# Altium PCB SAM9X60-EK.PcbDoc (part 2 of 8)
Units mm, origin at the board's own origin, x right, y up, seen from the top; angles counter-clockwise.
Board outline 150 x 125 mm, 4 copper layers (L1 - Top Layer, L2 - GND, L3 - PWR, L4 - Bottom Layer), stack 1.52 mm thick; 566 components, 500 nets, 2132 pads, 1038 vias.
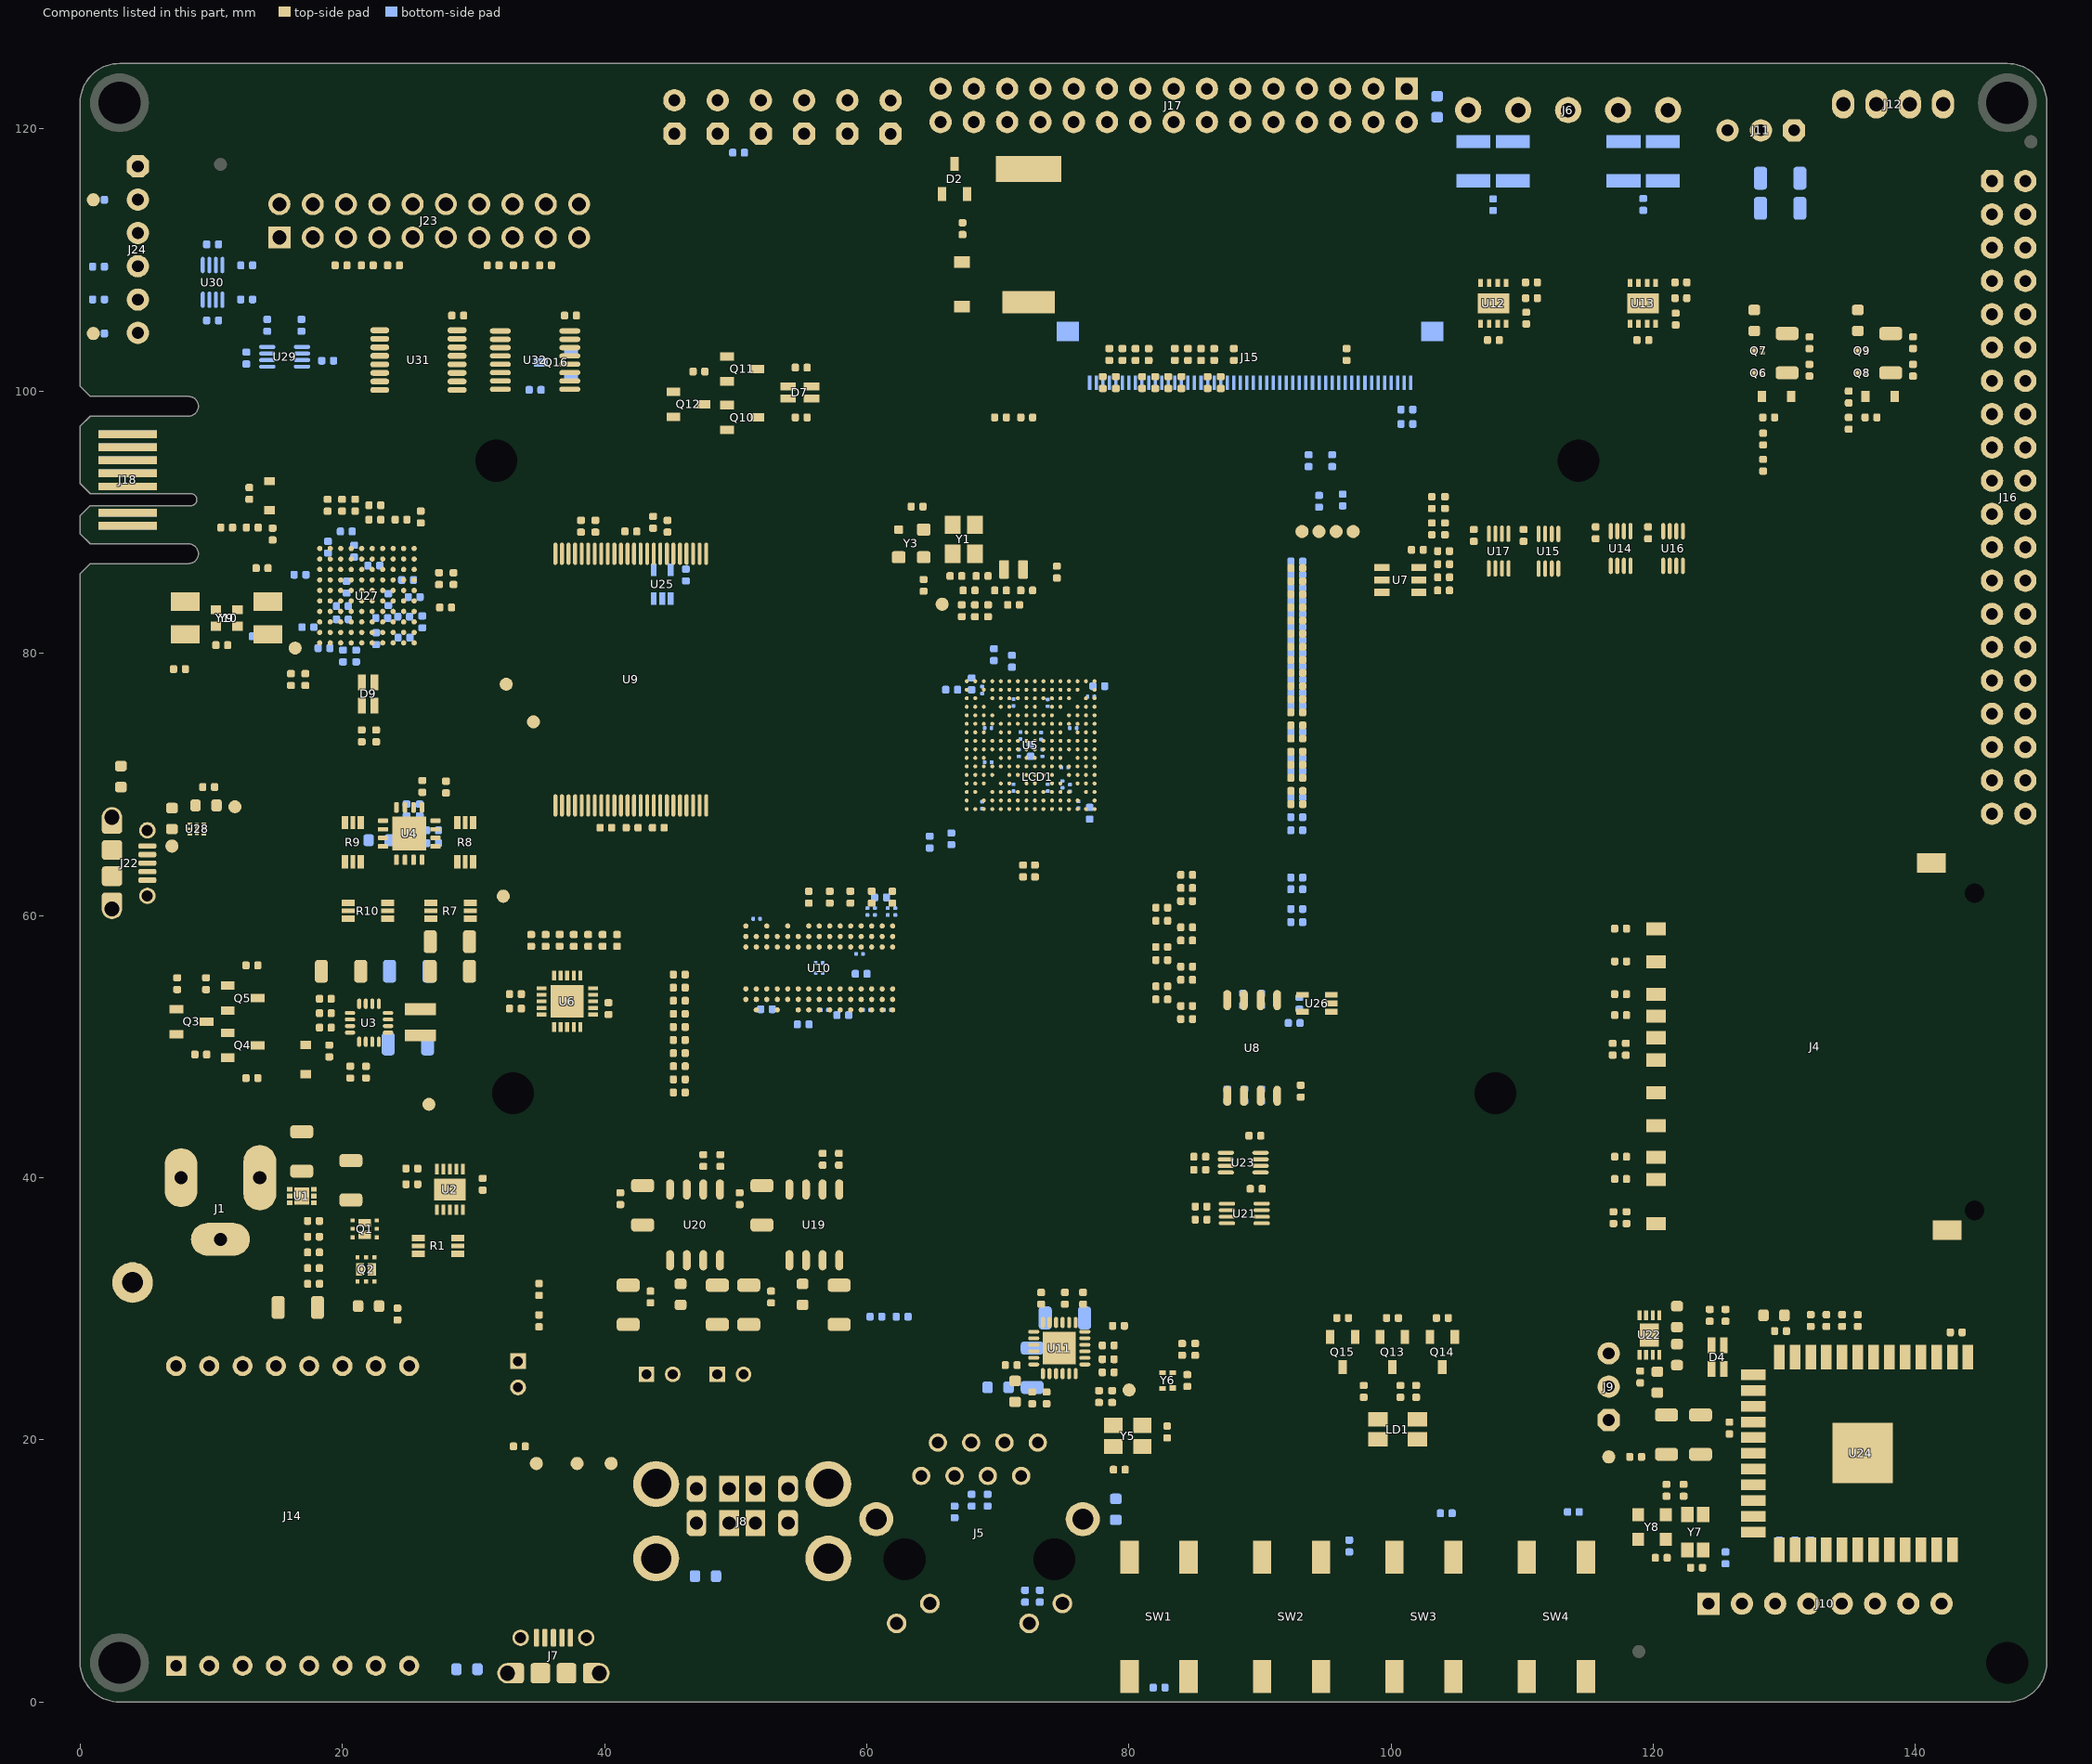
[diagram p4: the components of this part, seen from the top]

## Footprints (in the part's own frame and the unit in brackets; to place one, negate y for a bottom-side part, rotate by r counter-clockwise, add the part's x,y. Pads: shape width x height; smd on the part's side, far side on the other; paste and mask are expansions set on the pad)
10067847-001RLF [mm]
  rect 1x1.5 smd: 1(6.475,12.15) 2(3.975,12.15) 3(0.675,12.15) 4(-1.025,12.15) 5(-3.525,12.15) 6(-6.025,12.15) 7(-8.45,12.15) 8(-10.15,12.15) 9(8.975,12.15) 10(2.325,12.15) 11(-13.5,12.15)
  round 0 hole 1.5 unplated mask+0.05: 1.5mm(-12.5,-12.15) 1.5mm(11.7,-12.15)
  rect 1.5x2.2 smd: 12(-14,-10.05) 12(14,-8.85)
  L1 - Top Layer keep-out region: 8.425,1.05 9.525,1.05 9.525,3.05 8.425,3.05
  L1 - Top Layer keep-out region: 0.55,2.75 2.45,2.75 2.45,5.25 0.55,5.25
  L1 - Top Layer keep-out region: 5.925,3.55 7.025,3.55 7.025,6.05 5.925,6.05
  L1 - Top Layer keep-out region: 3.425,3.25 4.525,3.25 4.525,5.25 3.425,5.25
  L1 - Top Layer keep-out region: -1.575,2.75 -0.475,2.75 -0.475,4.75 -1.575,4.75
  L1 - Top Layer keep-out region: -4.075,3.15 -2.975,3.15 -2.975,5.15 -4.075,5.15
  L1 - Top Layer keep-out region: -6.575,3.15 -5.475,3.15 -5.475,5.15 -6.575,5.15
  L1 - Top Layer keep-out region: -15.1,-3.948 -13.9,-3.948 -13.9,2.352 -15.1,2.352
  L1 - Top Layer keep-out region: -9,3.15 -7.9,3.15 -7.9,5.15 -9,5.15
  L1 - Top Layer keep-out region: -10.7,3.15 -9.6,3.15 -9.6,5.15 -10.7,5.15
  silkscreen extent -15,-17.85 15,13.3, body extent -14.23,-17.65 14.22,12.6, height 2.9
"BUMP_ ESSENTRA_RBS-35_CYLINDRICAL_CLEAR_D9.50H4.8" [mm] "ESSENTRA Bumpon Rubber Pad D9.5H4.8"
  silkscreen extent -4.95,-4.95 4.95,4.95, body extent -4.77,-4.75 4.72,4.75, height 4.8
CAP_AX_P8.3L11.7D6.8H1.8 [mm]
  rect 5x2 smd: 1(0,5.075)
  rect 4x1.7 smd: 2(0,-5.075)
  silkscreen extent -3.5,-3.57 3.83,5.31, body extent -3.4,-5.73 3.4,5.58, height 1.71
CAP_C_0201 [mm] "Chip Capacitor, 2-Leads, Body 0.6x0.3mm, IPC Medium Density"
  rrect50% 0.275x0.3 smd mask+0.064: 1(-0.262,0) 2(0.262,0)
  body extent -0.3,-0.15 0.3,0.15, height 0.28
CAP_C_0402 [mm] "Chip Capacitor, 2-Leads, Body 1.0x0.5mm, IPC High Density"
  rrect50% 0.55x0.6 smd: 1(-0.45,0) 2(0.45,0)
  body extent -0.5,-0.3 0.5,0.3, height 0.2
CAP_C_0603 [mm] "Chip Capacitor, 2-Leads, Body 1.6x0.8mm, IPC Medium Density"
  rrect50% 0.8x0.9 smd: 1(-0.8,0) 2(0.8,0)
  silkscreen extent -0.1,-0.37 0.1,0.38, body extent -0.8,-0.4 0.8,0.4, height 0.3
CAP_C_1206 [mm] "Chip Capacitor, 2-Leads, Body 3.2x1.6mm, IPC Medium Density"
  rrect50% 1x1.75 smd: 1(-1.5,0) 2(1.5,0)
  silkscreen extent -0.6,-0.77 0.6,0.77, body extent -1.6,-0.8 1.6,0.8, height 1
CAP_RAD_P2D5H12.5 [mm] "Capacitor, Electrolytic, Radial; Body P=2.0mm, D=5mm, H=12.5mm"
  rect 1.2x1.2 hole 0.75: 1(-1,0)
  round 1.2 hole 0.75: 2(1,0)
  silkscreen extent -2.5,-2.5 2.5,2.5, body extent -2.5,-2.5 2.5,2.5, height 12.5
CDFN-4_3.2X2.5 [mil] "Oscillator DSC60X1C"
  rrect30% 26x26 smd: 1(-37.5,41.5)
  rrect30% 40x36 smd paste-2: 2(-37.5,-41.5) 3(37.5,-41.5) 4(37.5,41.5)
  L1 - Top Layer region: -53.5,23.5 -55.03,23.8 -56.33,24.67 -57.2,25.97 -57.5,27.5 -57.5,27.5 -57.5,55.5 -57.2,57.03 -56.33,58.33 -55.03,59.2 -53.5,59.5 -53.5,59.5 -27.5,59.5 -17.5,49.5 -17.5,27.5 -17.8,25.97 -18.67,24.67 -19.97,23.8 -21.5,23.5 -21.5,23.5
  silkscreen extent -68,-73 68,73, body extent -49,-63 49,63, height 34
CON_EDGE-CARD_PCB_RA_MEC1-108-02-F-D-RA1-SL [mm] "connector matching PCB pads"
  rect 0.6x4.45 smd far side paste-1 mask+0.05: 1(0,0) 3(-1,0) 7(-3,0) 9(-4,0) 11(-5,0) 13(-6,0) 15(-7,0)
  rect 0.6x4.45 smd paste-1 mask+0.05: 2(0,0) 4(-1,0) 8(-3,0) 10(-4,0) 12(-5,0) 14(-6,0) 16(-7,0)
  Keep-Out Layer lines w0.05: 3.655,-3.625 2.88,-2.85 2.88,4.64 ccw(c2.13,4.64) 1.38,4.64 1.38,-2.85 0.605,-3.625 -0.763,-3.625 -1.538,-2.85 -1.538,4.818 ccw(c-1.995,4.818) -2.452,4.818 -2.452,-2.85 ; -10.645,-3.625 -9.87,-2.85 -9.87,4.64 cw(c-9.12,4.64) -8.37,4.64 -8.37,-2.85 -7.595,-3.625 -3.227,-3.625 -2.452,-2.85 ; -2.451,-2.85 -2.452,-2.85
  body extent -7.3,-2.22 0.3,2.23, height 0.02
CON_FFC_0.5_FEMALE_1X50_SMD_OMR_XF2M-5015-1A [mm] "CONN FFC TOP/BOTTOM 50POS 0.50MM R/A"
  rect 0.25x1.1 smd: 1(12.25,-1.841) 2(11.75,-1.841) 3(11.25,-1.841) 4(10.75,-1.841) 5(10.25,-1.841) 6(9.75,-1.841) 7(9.25,-1.841) 8(8.75,-1.841) 9(8.25,-1.841) 10(7.75,-1.841) 11(7.25,-1.841) 12(6.75,-1.841) 13(6.25,-1.841) 14(5.75,-1.841) 15(5.25,-1.841) 16(4.75,-1.841) 17(4.25,-1.841) 18(3.75,-1.841) 19(3.25,-1.841) 20(2.75,-1.841) 21(2.25,-1.841) 22(1.75,-1.841) 23(1.25,-1.841) 24(0.75,-1.841) 25(0.25,-1.841) 26(-0.25,-1.841) 27(-0.75,-1.841) 28(-1.25,-1.841) 29(-1.75,-1.841) 30(-2.25,-1.841) 31(-2.75,-1.841) 32(-3.25,-1.841) 33(-3.75,-1.841) 34(-4.25,-1.841) 35(-4.75,-1.841) 36(-5.25,-1.841) 37(-5.75,-1.841) 38(-6.25,-1.841) 39(-6.75,-1.841) 40(-7.25,-1.841) 41(-7.75,-1.841) 42(-8.25,-1.841) 43(-8.75,-1.841) 44(-9.25,-1.841) 45(-9.75,-1.841) 46(-10.25,-1.841) 47(-10.75,-1.841) 48(-11.25,-1.841) 49(-11.75,-1.841) 50(-12.25,-1.841)
  rect 1.7x1.5 smd: MNT(-13.9,2.059) MNT(13.9,2.059)
  silkscreen extent -14.25,-1.89 14.25,0.56, body extent -14.55,-2.9 14.55,3, height 2
CON_JACK_POWER_TH_RA_MPD_EJ508A [mm] "CONN POWER JACK MALE 2.1MM CLSD"
  oval 2.5x5 hole 1 slot 3.5 at 90 deg: 1(3,0)
  oval 2.5x4.5 hole 1 slot 3 at 90 deg: 2(-3,0)
  oval 4.5x2.5 hole 1 slot 3 at 0 deg: 3(0,-4.7)
  silkscreen extent -10.79,-4.5 3.7,4.5, body extent -10.7,-4.9 3.7,4.5, height 11.1
CON_TERMINAL_2.54_1x4_TH_RA_PHO_1725672 [mm] "Terminal Block 2.54mm Pitch 1x4 PHO 1725672"
  oval 1.7x2.2 hole 1.1: 1(-3.81,0) 2(-1.27,0) 3(1.27,0) 4(3.81,0)
  silkscreen extent -5.51,-3.45 5.51,3.45, body extent -5.1,-2.99 5.2,3.23, height 8.64
CON_TERMINAL_3.81_1x5_TH_RA_PHO_1727049 [mm]
  round 2 hole 1.1: 1(-7.62,0) 2(-3.81,0) 3(0,0) 4(3.81,0) 5(7.62,0)
  silkscreen extent -9.91,-4.06 9.91,3.94, body extent -9.53,-3.74 9.52,3.56, height 8.5
CON_TP_TH_V_BLK_KEC_5011 [mm] "TEST POINT PC MULTI PURPOSE BLK"
  round 3.1 hole 1.6: 1(0,0)
  silkscreen extent -1.85,-1.85 1.85,1.85, body extent -1.59,-1.59 1.59,1.59, height 8.13
CON_USB2.0-A_Dual_RCPT_TH_RA_AMN_AU-Y1008-2 [mm] "CONN USB 2.0 A DUAL RCPT TH R/A L=17.5mm, W=14.5mm, H=15.7mm"
  round 3.5 hole 2.3: 0(-6.57,-2.84) 0(-6.57,2.84) 0(6.57,-2.84) 0(6.57,2.84)
  rrect50% 1.5x2 hole 1: 1(-3.5,2.49) 4(3.5,2.49) 5(-3.5,-0.13) 8(3.5,-0.13)
  rect 1.5x2 hole 1: 2(-1,2.49) 3(1,2.49) 6(-1,-0.13) 7(1,-0.13)
  silkscreen extent -6.8,-13.34 6.8,4.56, body extent -7.85,-13.74 7.85,3.86, height 16.2
CON_USB_MICRO-AB_SMD_TH_RA_FCI_10118194-0001LF [mm] "FCI USB Micro-AB SMD RA L5W8.8H2.8"
  round 1.55 hole 1.15: 0(-3.505,0) 0(3.505,0)
  rrect30% 1.5x1.55 smd paste-0.051: 0(-3,0) 0(-1,0) 0(1,0) 0(3,0)
  round 1.25 hole 0.85: 0(-2.5,-2.7) 0(2.5,-2.7)
  rrect50% 0.4x1.35 smd paste-0.046 mask+0.05: 1(1.3,-2.7) 2(0.65,-2.7) 3(0,-2.7) 4(-0.65,-2.7) 5(-1.3,-2.7)
  Keep-Out Layer board cut-out: 3.81,1.452 4.102,1.51 4.349,1.675 4.514,1.922 4.572,2.214 4.572,2.214 4.514,2.505 4.349,2.753 4.102,2.918 3.81,2.976 3.81,2.976 -3.81,2.976 -4.102,2.918 -4.349,2.753 -4.514,2.505 -4.572,2.214 -4.572,2.214 -4.514,1.922 -4.349,1.675 -4.102,1.51 -3.81,1.452 -3.81,1.452
  Keep-Out Layer board cut-out: 3.81,1.452 4.102,1.51 4.349,1.675 4.514,1.922 4.572,2.214 4.572,2.214 4.514,2.505 4.349,2.753 4.102,2.918 3.81,2.976 3.81,2.976 -3.81,2.976 -4.102,2.918 -4.349,2.753 -4.514,2.505 -4.572,2.214 -4.572,2.214 -4.514,1.922 -4.349,1.675 -4.102,1.51 -3.81,1.452 -3.81,1.452
  silkscreen extent -4.22,-3.1 4.23,-1.07, body extent -4.02,-2.89 4.02,2.69, height 2.74
CRYSTAL_ABM8G [mil]
  rect 55x47 smd: 1(-43.5,-33.5) 2(43.5,-33.5) 3(43.5,33.5) 4(-43.5,33.5)
  silkscreen extent -81,-67 81,67, body extent -63,-49 63,49, height 40
CRYSTAL_ABS06 [mm] "Crystal Abracon ABS07"
  rrect20% 0.75x1.4 smd: 1(-0.725,0) 2(0.725,0)
  silkscreen extent -1.35,-0.95 1.35,0.95, body extent -1,-0.61 1,0.61, height 0.6
CRYSTAL_L3.2W2.5H0.8 [mm] "L=3.2mm, W=2.5mm, H=0.8mm"
  rect 1.4x1.15 smd: 1(-1.1,-0.8) 2(1.1,-0.8) 3(1.1,0.8) 4(-1.1,0.8)
  silkscreen extent -2.1,-1.68 2.1,1.68, body extent -1.6,-1.25 1.6,1.25, height 0.8
CRYSTAL_L7.5W5.2H1.4 [mm]
  rect 2.2x1.4 smd: 1(-3.15,-1.25) 2(-3.15,1.25) 3(3.15,1.25) 4(3.15,-1.25)
  silkscreen extent -4,-2.9 4,2.9, body extent -3.7,-2.6 3.7,2.6, height 1.45
"DFN-4_VFLGA_1.6 X 1.2" [mm] "DFN, 4-Leads, Body 1.60x1.20mm, Pitch 1.25mm, IPC Medium Density"
  rect 0.43x0.5 smd: 1(-0.56,-0.375)
  rect 0.35x0.5 smd: 2(0.6,-0.375) 3(0.6,0.375) 4(-0.6,0.375)
  silkscreen extent -0.9,-0.95 0.9,0.95, body extent -0.8,-0.6 0.8,0.6, height 0.61
DFN-6_1.2X1.2 [mm] "DFN, 6-Leads, Body 1.2x1.2mm (max), Pitch 0.65"
  rect 0.18x0.35 smd: 1(-0.4,-0.525) 2(0,-0.525) 3(0.4,-0.525) 4(0.4,0.525) 5(0,0.525) 6(-0.4,0.525)
  rect 0.94x0.3 smd: 7(0,0)
  silkscreen extent -1,-0.4 1,0.4, body extent -0.62,-0.62 0.63,0.63, height 0.6
DFN-6_2x1.6_EP0.4x0.35 [mm] "DFN, 6-Leads, Body 2x1.6mm (max), Pitch 0.5"
  rect 0.36x0.43 smd mask+0.038: 1(-0.5,-0.925) 2(0,-0.925) 3(0.5,-0.925) 4(0.5,0.925) 5(0,0.925) 6(-0.5,0.925)
  rect 1.3x1.15 smd mask+0.038: 7(0,0)
  silkscreen extent -0.95,-0.4 0.95,0.4, body extent -0.8,-1 0.8,1, height 1
DFN-8_2x3 [mm] "DFN, 8-Leads, Body 3.0x2.0mm (max), Pitch 0.5"
  rect 0.3x0.75 smd mask+0.05: 1(-0.75,-1.5) 2(-0.25,-1.5) 3(0.25,-1.5) 4(0.75,-1.5) 5(0.75,1.5) 6(0.25,1.5) 7(-0.25,1.5) 8(-0.75,1.5)
  rect 1.45x1.75 smd mask+0.075: 9(0,0)
  silkscreen extent -1.1,-0.8 1.1,0.8, body extent -1,-1.5 1,1.5, height 1
DFN-8_3x3_EP2.4X1.55 [mm] "DFN, 8-Leads, Body 3.0x3.0mm (max), Pitch 0.65mm, IPC Medium Density"
  rect 0.35x0.6 smd: 1(-0.975,-1.55) 2(-0.325,-1.55) 3(0.325,-1.55) 4(0.975,-1.55) 5(0.975,1.55) 6(0.325,1.55) 7(-0.325,1.55) 8(-0.975,1.55)
  rect 2.4x1.55 smd: 9(0,0)
  silkscreen extent -1.6,-1.5 1.6,1.5, body extent -1.5,-1.5 1.5,1.5, height 0.61
DFN-10_3x3 [mm] "DFN, 10-Leads, Body 3.0x3.0mm (max), Pitch 0.50mm, IPC Medium Density"
  rect 0.8x0.3 smd paste-0.038 mask+0.05: 1(-1.55,1) 2(-1.55,0.5) 3(-1.55,0) 4(-1.55,-0.5) 5(-1.55,-1) 6(1.55,-1) 7(1.55,-0.5) 8(1.55,0) 9(1.55,0.5) 10(1.55,1)
  rect 1.65x2.38 smd paste-0.305: 11(0,0)
  silkscreen extent -1.6,-1.6 1.6,1.6, body extent -1.56,-1.55 1.56,1.55, height 0.8
HDR_F_2.54_1x3 [mm]
  oct 1.7x1.7 hole 0.9: 1(-2.54,0)
  round 1.7 hole 0.9: 2(0,0) 3(2.54,0)
  silkscreen extent -4,-1.5 4,1.5, body extent -3.81,-1.27 3.81,1.27, height 6.02
HDR_F_2.54_1X8 [mm] "Header Female Vertical 8 Way 2.54mm Pitch"
  rect 1.7x1.7 hole 0.9: 1(-8.89,0)
  round 1.7 hole 0.9: 2(-6.35,0) 3(-3.81,0) 4(-1.27,0) 5(1.27,0) 6(3.81,0) 7(6.35,0) 8(8.89,0)
  silkscreen extent -10.61,-1.4 10.59,1.4, body extent -10.41,-1.21 10.42,1.21, height 8.51
HDR_M_2.54_1x2 [mm] "Header Male Vertical 4 Way 2.54mm Pitch"
  oct 1.7x1.7 hole 0.9: 1(-1.27,0)
  round 1.7 hole 0.9: 2(1.27,0)
  silkscreen extent -2.6,-1.35 2.6,1.4, body extent -2.54,-1.27 2.54,1.27, height 5.94
HDR_M_2.54_1x3 [mm] "Header Male Vertical 4 Way P=2.54mm"
  oct 1.7x1.7 hole 0.9: 1(-2.54,0)
  round 1.7 hole 0.9: 2(0,0) 3(2.54,0)
  silkscreen extent -3.94,-1.4 3.96,1.4, body extent -3.8,-1.26 3.82,1.28, height 5.94
HDR_M_2.54_1x6 [mm] "Header Male Vertical 6 Way 2.54mm Pitch"
  oct 1.7x1.7 hole 0.9: 1(-6.35,0)
  round 1.7 hole 0.9: 2(-3.81,0) 3(-1.27,0) 4(1.27,0) 5(3.81,0) 6(6.35,0)
  silkscreen extent -7.75,-1.4 7.7,1.4, body extent -7.62,-1.27 7.62,1.27, height 8.38
HDR_M_2.54_2X10_S_TH_RA_OS_302-R201 [mil] "20 Positions Header Connector 0.100\" (2.54mm) Through Hole Gold"
  rect 66x66 hole 42: 1(-450,-50)
  round 66 hole 42: 2(-450,50) 3(-350,-50) 4(-350,50) 5(-250,-50) 6(-250,50) 7(-150,-50) 8(-150,50) 9(-50,-50) 10(-50,50) 11(50,-50) 12(50,50) 13(150,-50) 14(150,50) 15(250,-50) 16(250,50) 17(350,-50) 18(350,50) 19(450,-50) 20(450,50)
  silkscreen extent -658,-98 658,480, body extent -651,-63 651,471, height 359
HDR_M_2.54_2x15 [mm] "Header Male Vertical 2x10 Way 2.54mm Pitch"
  rect 1.7x1.7 hole 0.9: 1(-17.788,-1.27)
  round 1.7 hole 0.9: 2(-17.788,1.27) 3(-15.248,-1.27) 4(-15.248,1.27) 5(-12.708,-1.27) 6(-12.708,1.27) 7(-10.168,-1.27) 8(-10.168,1.27) 9(-7.628,-1.27) 10(-7.628,1.27) 11(-5.088,-1.27) 12(-5.088,1.27) 13(-2.548,-1.27) 14(-2.548,1.27) 15(-0.008,-1.27) 16(-0.008,1.27) 17(2.532,-1.27) 18(2.532,1.27) 19(5.072,-1.27) 20(5.072,1.27) 21(7.612,-1.27) 22(7.612,1.27) 23(10.152,-1.27) 24(10.152,1.27) 25(12.692,-1.27) 26(12.692,1.27) 27(15.232,-1.27) 28(15.232,1.27) 29(17.772,-1.27) 30(17.772,1.27)
  silkscreen extent -19.31,-2.79 19.42,2.79, body extent -19.06,-2.54 19.04,2.54, height 8.5
HDR_M_2.54_2x20 [mm] "Header Male Vertical 2x20 Way 2.54mm Pitch"
  oct 1.7x1.7 hole 0.9: 1(-24.13,-1.27)
  round 1.7 hole 0.9: 2(-24.13,1.27) 3(-21.59,-1.27) 4(-21.59,1.27) 5(-19.05,-1.27) 6(-19.05,1.27) 7(-16.51,-1.27) 8(-16.51,1.27) 9(-13.97,-1.27) 10(-13.97,1.27) 11(-11.43,-1.27) 12(-11.43,1.27) 13(-8.89,-1.27) 14(-8.89,1.27) 15(-6.35,-1.27) 16(-6.35,1.27) 17(-3.81,-1.27) 18(-3.81,1.27) 19(-1.27,-1.27) 20(-1.27,1.27) 21(1.27,-1.27) 22(1.27,1.27) 23(3.81,-1.27) 24(3.81,1.27) 25(6.35,-1.27) 26(6.35,1.27) 27(8.89,-1.27) 28(8.89,1.27) 29(11.43,-1.27) 30(11.43,1.27) 31(13.97,-1.27) 32(13.97,1.27) 33(16.51,-1.27) 34(16.51,1.27) 35(19.05,-1.27) 36(19.05,1.27) 37(21.59,-1.27) 38(21.59,1.27) 39(24.13,-1.27) 40(24.13,1.27)
  silkscreen extent -25.4,-2.54 25.4,2.54, body extent -25.4,-2.54 25.4,2.54, height 8.38
IND_C_0603 [mm] "Chip Inductor, 2-Leads, Body 1.6x0.8mm, IPC Medium Density"
  rrect50% 0.8x0.9 smd: 1(-0.8,0) 2(0.8,0)
  silkscreen extent -0.1,-0.35 0.1,0.35, body extent -0.8,-0.4 0.8,0.4, height 0.95
IND_C_1008 [mm]
  rect 0.9x2.4 smd mask+0.075: 1(-1,0) 2(1,0)
  silkscreen extent -0.25,-1.1 0.25,1.1, body extent -1.24,-1 1.26,1, height 1.2
J00-0045NL_RJ45_connector [mm] "J00-0061NL_RJ45_connector"
  round 1.4 / inner round 1.524 / far side round 1.4 hole 0.9: 1(-4.445,6.35) 2(-3.175,8.89) 3(-1.905,6.35) 4(-0.635,8.89) 5(0.635,6.35) 6(1.905,8.89) 7(3.175,6.35) 8(4.445,8.89)
  round 1.5 / inner round 1.524 / far side round 1.4 hole 1: 9(-6.325,-4.9) 10(-3.785,-3.38) 11(3.785,-4.9) 12(6.325,-3.38)
  round 2.6 / inner round 1.524 / far side round 2.6 hole 1.6: 13(-7.875,3.05) 14(7.875,3.05)
  round 2.3 / inner round 1.524 / far side round 2.3 hole 3.2 unplated: MH1(-5.715,0)
  round 2 / inner round 1.524 / far side round 2 hole 3.2 unplated: MH2(5.715,0)
  silkscreen extent -8.51,-11.3 8.51,11.05, body extent -8.12,-10.9 8.12,10.77, height 13.74
LABEL_Need_Help_Large [mm] "Need Help Label with Serial Number"
  silkscreen extent -25.4,-6.35 25.4,6.35, body extent -25.4,-6.35 25.4,6.35, height 0.3
LED_DUAL_SMD_2x1.25mm [mm] "LED 2X1.2MM RD/GN WTR CLR SMD"
  rect 1.2x0.6 smd: 1(0.9,0.475) 2(-0.9,0.475) 3(-0.9,-0.475) 4(0.9,-0.475)
  silkscreen extent -2.16,-1.07 1.8,1.08, body extent -0.81,-0.75 0.81,0.75, height 0.6
"MODULE ATWILC3000-MR110CA" [mm]
  rect 1.88x0.813 smd paste-9: 1(-7.31,8.05) 2(-7.31,6.85) 3(-7.31,5.65) 4(-7.31,4.45) 5(-7.31,3.25) 6(-7.31,2.05) 7(-7.31,0.85) 8(-7.31,-0.35) 9(-7.31,-1.55) 10(-7.31,-2.75) 11(-7.31,-3.95) 12(-7.31,-5.15) 13(-7.31,-6.35) 25(7.37,-6.35) 26(7.37,-5.15) 27(7.37,-3.95) 28(7.37,-2.75) 29(7.37,-1.55) 30(7.37,-0.35) 31(7.37,0.85) 32(7.37,2.05) 33(7.37,3.25) 34(7.37,4.45) 35(7.37,5.65) 36(7.37,6.85)
  rect 0.813x1.88 smd paste-9: 14(-5.97,-8.33) 15(-4.77,-8.33) 16(-3.57,-8.33) 17(-2.37,-8.33) 18(-1.17,-8.33) 19(0.03,-8.33) 20(1.23,-8.33) 21(2.43,-8.33) 22(3.63,-8.33) 23(4.83,-8.33) 24(6.03,-8.33)
  rect 4.6x4.6 smd paste-9: 37(0,0)
  silkscreen extent -7.75,-8.75 7.75,14.25, body extent -7.31,-8.33 7.37,14.05, height 2.73
OSCILLATOR_ASH7KW_L3.2W1.5H1 [mm]
  rect 0.95x1.15 smd: 1(-0.6,1.35) 2(-0.6,-1.35) 3(0.6,-1.35) 4(0.6,1.35)
  silkscreen extent -1,-0.53 1.05,0.52, body extent -0.75,-1.6 0.75,1.6, height 1
OSCILLATOR_DSC1001_L3.2W2.5H0.85 [mm] "Oscillator DSC1001"
  rect 0.9x1 smd: 1(-1.05,-0.95) 2(1.05,-0.95) 3(1.05,0.95) 4(-1.05,0.95)
  silkscreen extent -1.7,-1.35 1.7,1.35, body extent -1.6,-1.25 1.6,1.25, height 0.86
OSCILLATOR_DSC60000L2.5W2.0H0.89 [mm]
  rect 0.8x0.7 smd: 1(-0.825,-0.625) 2(0.825,-0.625) 3(0.825,0.625) 4(-0.825,0.625)
  silkscreen extent -1.5,-1.25 1.5,1.25, body extent -1.28,-0.97 1.22,1.03, height 0.82
PLCC-4_CLV1A-FKB [mm] "PLCC4 3 in 1 SMD LED"
  rect 1.5x1.1 smd: 1(-1.5,0.75) 2(-1.5,-0.75) 3(1.5,-0.75) 4(1.5,0.75)
  silkscreen extent -2.5,-1.55 2.5,1.55, body extent -1.75,-1.4 1.75,1.4, height 1.9
QFN-16_3X3 [mm] "QFN 16 pin P=0.5mm, L=3mm, W=3mm, H=0.9mm"
  oval 0.8x0.3 smd mask+0.05: 1(-1.45,0.75) 2(-1.45,0.25) 3(-1.45,-0.25) 4(-1.45,-0.75) 9(1.45,-0.75) 10(1.45,-0.25) 11(1.45,0.25) 12(1.45,0.75)
  oval 0.3x0.8 smd mask+0.05: 5(-0.75,-1.45) 6(-0.25,-1.45) 7(0.25,-1.45) 8(0.75,-1.45) 13(0.75,1.45) 14(0.25,1.45) 15(-0.25,1.45) 16(-0.75,1.45)
  silkscreen extent -1.7,-1.7 1.7,1.7, body extent -1.5,-1.5 1.5,1.5, height 0.9
QFN-20_4x4 [mm]
  rect 0.73x0.3 smd paste-0.075: 1(-1.965,1) 2(-1.965,0.5) 3(-1.965,0) 4(-1.965,-0.5) 5(-1.965,-1) 11(1.965,-1) 12(1.965,-0.5) 13(1.965,0) 14(1.965,0.5) 15(1.965,1)
  rect 0.3x0.73 smd paste-0.075: 6(-1,-1.965) 7(-0.5,-1.965) 8(0,-1.965) 9(0.5,-1.965) 10(1,-1.965) 16(1,1.965) 17(0.5,1.965) 18(0,1.965) 19(-0.5,1.965) 20(-1,1.965)
  rect 2.5x2.5 smd paste-0.75: 21(0,0)
  silkscreen extent -2.1,-2.1 2.1,2.1, body extent -2.02,-2.02 2.02,2.02, height 0.8
QFN-24_4X4 [mm]
  oval 0.85x0.3 smd mask+0.05: 1(-1.95,1.25) 2(-1.95,0.75) 3(-1.95,0.25) 4(-1.95,-0.25) 5(-1.95,-0.75) 6(-1.95,-1.25) 13(1.95,-1.25) 14(1.95,-0.75) 15(1.95,-0.25) 16(1.95,0.25) 17(1.95,0.75) 18(1.95,1.25)
  oval 0.3x0.85 smd mask+0.05: 7(-1.25,-1.95) 8(-0.75,-1.95) 9(-0.25,-1.95) 10(0.25,-1.95) 11(0.75,-1.95) 12(1.25,-1.95) 19(1.25,1.95) 20(0.75,1.95) 21(0.25,1.95) 22(-0.25,1.95) 23(-0.75,1.95) 24(-1.25,1.95)
  rect 2.5x2.5 smd paste-0.33 mask+0.05: 25(0,0)
  silkscreen extent -2.15,-2.15 2.15,2.15, body extent -2,-2 2,2, height 0.9
QSOP-16 [mm] "QSOP 16-Leads"
  oval 1.6x0.4 smd mask+0.05: 1(-2.65,2.223) 2(-2.65,1.588) 3(-2.65,0.953) 4(-2.65,0.318) 5(-2.65,-0.317) 6(-2.65,-0.952) 7(-2.65,-1.587) 8(-2.65,-2.222) 9(2.65,-2.222) 10(2.65,-1.587) 11(2.65,-0.952) 12(2.65,-0.317) 13(2.65,0.318) 14(2.65,0.953) 15(2.65,1.588) 16(2.65,2.223)
  silkscreen extent -2.77,-2.5 1.5,3.12, body extent -3.01,-2.49 3.01,2.49, height 1.71
RES_C_0201 [mm] "Chip Resistor, 2-Leads, Body 0.6x0.3mm, IPC Medium Density"
  rrect50% 0.275x0.3 smd mask+0.064: 1(-0.262,0) 2(0.262,0)
  body extent -0.3,-0.15 0.3,0.15, height 0.22
RES_C_0402 [mm] "Chip Resistor, 2-Leads, Body 1.0x0.5mm, IPC Medium Density"
  rrect50% 0.55x0.6 smd: 1(-0.45,0) 2(0.45,0)
  body extent -0.5,-0.3 0.5,0.3, height 0.2
RES_C_0603 [mm] "Chip Resistor, 2-Leads, Body 1.6x0.8mm, IPC Medium Density"
  rrect50% 0.8x0.9 smd: 1(-0.8,0) 2(0.8,0)
  silkscreen extent -0.1,-0.37 0.1,0.37, body extent -0.8,-0.4 0.8,0.4, height 0.3
RES_C_1206_SHUNT#1 [mm] "Chip Resistor, 2-Leads, Body 3.2x1.6mm, IPC Medium Density"
  rect 1x0.5 smd: 1(-1.5,-0.6) 1(-1.5,0.6) 2(1.5,-0.6) 2(1.5,0.6)
  rect 1x0.35 smd: 3(-1.5,0) 4(1.5,0)
  silkscreen extent -0.6,-0.77 0.6,0.78, body extent -1.6,-0.8 1.6,0.8, height 1
RES_C_1206_SHUNT#2 [mm] "Chip Resistor, 2-Leads, Body 3.2x1.6mm, IPC Medium Density"
  rect 1x0.5 smd mask+0.05: 1(-1.5,-0.6) 1(-1.5,0.6) 2(1.5,-0.6) 2(1.5,0.6)
  rect 1x0.35 smd mask+0.05: 3(-1.5,0) 4(1.5,0)
  silkscreen extent -0.6,-0.77 0.6,0.78, body extent -1.6,-0.8 1.6,0.8, height 1
RES_C_1210 [mm] "Chip Resistor, 2-Leads, Body 3.2x2.5mm, IPC Medium Density"
  rect 1x2.6 smd: 1(-1.5,0) 2(1.5,0)
  silkscreen extent -0.7,-1.23 0.7,1.23, body extent -1.55,-1.3 1.55,1.3, height 0.57
"SAM9X60 TFBGA-228" [mm] "BGA, 228-Leads, Body 11.00 x 11.00mm x 1.20mm, Pitch 0.65mm"
  round 0.3 smd mask+0.05: A1(-4.875,4.875) A2(-4.225,4.875) A3(-3.575,4.875) A4(-2.925,4.875) A5(-2.275,4.875) A6(-1.625,4.875) A7(-0.975,4.875) A8(-0.325,4.875) A9(0.325,4.875) A10(0.975,4.875) A11(1.625,4.875) A12(2.275,4.875) A13(2.925,4.875) A14(3.575,4.875) A15(4.225,4.875) A16(4.875,4.875) B1(-4.875,4.225) B3(-3.575,4.225) B4(-2.925,4.225) B5(-2.275,4.225) B6(-1.625,4.225) B7(-0.975,4.225) B8(-0.325,4.225) B9(0.325,4.225) B10(0.975,4.225) B11(1.625,4.225) B12(2.275,4.225) B13(2.925,4.225) B14(3.575,4.225) B16(4.875,4.225) C1(-4.875,3.575) C2(-4.225,3.575) C4(-2.925,3.575) C5(-2.275,3.575) C6(-1.625,3.575) C7(-0.975,3.575) C8(-0.325,3.575) C9(0.325,3.575) C10(0.975,3.575) C11(1.625,3.575) C12(2.275,3.575) C13(2.925,3.575) C15(4.225,3.575) C16(4.875,3.575) D1(-4.875,2.925) D2(-4.225,2.925) D3(-3.575,2.925) D5(-2.275,2.925) D6(-1.625,2.925) D8(-0.325,2.925) D9(0.325,2.925) D11(1.625,2.925) D12(2.275,2.925) D14(3.575,2.925) D15(4.225,2.925) D16(4.875,2.925) E1(-4.875,2.275) E2(-4.225,2.275) E3(-3.575,2.275) E4(-2.925,2.275) E6(-1.625,2.275) E7(-0.975,2.275) E8(-0.325,2.275) E9(0.325,2.275) E10(0.975,2.275) E11(1.625,2.275) E13(2.925,2.275) E14(3.575,2.275) E15(4.225,2.275) E16(4.875,2.275) F1(-4.875,1.625) F2(-4.225,1.625) F3(-3.575,1.625) F4(-2.925,1.625) F5(-2.275,1.625) F6(-1.625,1.625) F7(-0.975,1.625) F8(-0.325,1.625) F9(0.325,1.625) F10(0.975,1.625) F11(1.625,1.625) F12(2.275,1.625) F13(2.925,1.625) F14(3.575,1.625) F15(4.225,1.625) F16(4.875,1.625) G1(-4.875,0.975) G2(-4.225,0.975) G3(-3.575,0.975) G5(-2.275,0.975) G6(-1.625,0.975) G8(-0.325,0.975) G9(0.325,0.975) G11(1.625,0.975) G12(2.275,0.975) G14(3.575,0.975) G15(4.225,0.975) G16(4.875,0.975) H1(-4.875,0.325) H2(-4.225,0.325) H3(-3.575,0.325) H4(-2.925,0.325) H5(-2.275,0.325) H6(-1.625,0.325) H7(-0.975,0.325) H8(-0.325,0.325) H9(0.325,0.325) H10(0.975,0.325) H11(1.625,0.325) H12(2.275,0.325) H13(2.925,0.325) H14(3.575,0.325) H15(4.225,0.325) H16(4.875,0.325) J1(-4.875,-0.325) J2(-4.225,-0.325) J3(-3.575,-0.325) J4(-2.925,-0.325) J5(-2.275,-0.325) J6(-1.625,-0.325) J7(-0.975,-0.325) J8(-0.325,-0.325) J9(0.325,-0.325) J10(0.975,-0.325) J11(1.625,-0.325) J12(2.275,-0.325) J13(2.925,-0.325) J14(3.575,-0.325) J15(4.225,-0.325) J16(4.875,-0.325) K1(-4.875,-0.975) K2(-4.225,-0.975) K3(-3.575,-0.975) K5(-2.275,-0.975) K6(-1.625,-0.975) K8(-0.325,-0.975) K9(0.325,-0.975) K11(1.625,-0.975) K12(2.275,-0.975) K14(3.575,-0.975) K15(4.225,-0.975) K16(4.875,-0.975) L1(-4.875,-1.625) L2(-4.225,-1.625) L3(-3.575,-1.625) L4(-2.925,-1.625) L5(-2.275,-1.625) L6(-1.625,-1.625) L7(-0.975,-1.625) L8(-0.325,-1.625) L9(0.325,-1.625) L10(0.975,-1.625) L11(1.625,-1.625) L12(2.275,-1.625) L13(2.925,-1.625) L14(3.575,-1.625) L15(4.225,-1.625) L16(4.875,-1.625) M1(-4.875,-2.275) M2(-4.225,-2.275) M3(-3.575,-2.275) M4(-2.925,-2.275) M6(-1.625,-2.275) M7(-0.975,-2.275) M8(-0.325,-2.275) M9(0.325,-2.275) M10(0.975,-2.275) M11(1.625,-2.275) M13(2.925,-2.275) M14(3.575,-2.275) M15(4.225,-2.275) M16(4.875,-2.275) N1(-4.875,-2.925) N2(-4.225,-2.925) N3(-3.575,-2.925) N5(-2.275,-2.925) N6(-1.625,-2.925) N8(-0.325,-2.925) N9(0.325,-2.925) N11(1.625,-2.925) N12(2.275,-2.925) N14(3.575,-2.925) N15(4.225,-2.925) N16(4.875,-2.925) P1(-4.875,-3.575) P2(-4.225,-3.575) P4(-2.925,-3.575) P5(-2.275,-3.575) P6(-1.625,-3.575) P7(-0.975,-3.575) P8(-0.325,-3.575) P9(0.325,-3.575) P10(0.975,-3.575) P11(1.625,-3.575) P12(2.275,-3.575) P13(2.925,-3.575) P15(4.225,-3.575) P16(4.875,-3.575) R1(-4.875,-4.225) R3(-3.575,-4.225) R4(-2.925,-4.225) R5(-2.275,-4.225) R6(-1.625,-4.225) R7(-0.975,-4.225) R8(-0.325,-4.225) R9(0.325,-4.225) R10(0.975,-4.225) R11(1.625,-4.225) R12(2.275,-4.225) R13(2.925,-4.225) R14(3.575,-4.225) R16(4.875,-4.225) T1(-4.875,-4.875) T2(-4.225,-4.875) T3(-3.575,-4.875) T4(-2.925,-4.875) T5(-2.275,-4.875) T6(-1.625,-4.875) T7(-0.975,-4.875) T8(-0.325,-4.875) T9(0.325,-4.875) T10(0.975,-4.875) T11(1.625,-4.875) T12(2.275,-4.875) T13(2.925,-4.875) T14(3.575,-4.875) T15(4.225,-4.875) T16(4.875,-4.875)
  silkscreen extent -5.8,-5.8 5.8,5.8, body extent -5.5,-5.5 5.5,5.5, height 1.2
SC-70-5#1 [mm]
  rect 0.45x0.95 smd mask+0.05: 1(-0.65,-1.1) 2(0,-1.1) 3(0.65,-1.1) 4(0.65,1.1) 5(-0.65,1.1)
  silkscreen extent -1.1,-0.33 1.1,0.33, body extent -1,-1.05 1,1.05, height 0.95
SC-70-5#2 [mm]
  rect 0.45x0.95 smd: 1(-0.65,-1.1) 2(0,-1.1) 3(0.65,-1.1) 4(0.65,1.1) 5(-0.65,1.1)
  silkscreen extent -1.1,-0.33 1.1,0.33, body extent -1,-1.05 1,1.05, height 0.95
"SIA923AEDJ PPAK_SC70_6L" [mm] "6-Leads SC70 Dual pad, 2.05mm x 2.05mm package"
  rect 0.325x0.3 smd mask+0.05: 1(-0.913,0.65) 2(-0.913,0) 3(-0.913,-0.65) 4(0.913,-0.65) 5(0.913,0) 6(0.913,0.65)
  rect 0.95x0.613 smd mask+0.05: 7(0,0.455) 8(0,-0.455)
  silkscreen extent -1.38,-1.1 1.38,1.1, body extent -1.02,-1.02 1.02,1.02, height 0.8
SOCKET_MIKROBUS_F_2.54_2X8_V_25.4X21 [mil]
  rect 60x60 hole 35: 1(-450,350)
  round 60 hole 35: 2(-450,250) 3(-450,150) 4(-450,50) 5(-450,-50) 6(-450,-150) 7(-450,-250) 8(-450,-350) 9(450,-350) 10(450,-250) 11(450,-150) 12(450,-50) 13(450,50) 14(450,150) 15(450,250) 16(450,350)
  silkscreen extent -550,-550 550,588, body extent -495,-410 498,410, height 335
SOD-123 [mm] "Diode SOD-123 Body L=2.85, W= 1.8"
  rect 0.9x1.2 smd: 1(-1.7,0) 2(1.7,0)
  silkscreen extent -1.87,-1.05 2.02,1.05, body extent -1.93,-0.85 1.93,0.85, height 1.43
SOD-323 [mm] "Molded Diode, 2-Leads, Body 1.8x1.4mm, IPC Medium Density"
  rect 0.63x0.83 smd: 1(-1.115,0) 2(1.115,0)
  silkscreen extent -0.17,-0.7 1.73,0.7, body extent -1.3,-0.68 1.3,0.67, height 1.1
SOIC-8 [mm] "SOIC, 8-Leads, Overall 4.9x6mm, Pitch 1.27mm, IPC Medium Density"
  oval 1.55x0.6 smd: 1(-2.7,1.905) 2(-2.7,0.635) 3(-2.7,-0.635) 4(-2.7,-1.905) 5(2.7,-1.905) 6(2.7,-0.635) 7(2.7,0.635) 8(2.7,1.905)
  silkscreen extent -1.6,-2.5 1.6,2.5, body extent -3.01,-2.5 3.01,2.5, height 1.75
SOIJ-8 [mm] "SOIC, 8-Leads, Overall 4.9x6mm, Pitch 1.27mm, IPC Medium Density"
  oval 1.55x0.6 smd: 1(-3.65,1.905) 2(-3.65,0.635) 3(-3.65,-0.635) 4(-3.65,-1.905) 5(3.65,-1.905) 6(3.65,-0.635) 7(3.65,0.635) 8(3.65,1.905)
  silkscreen extent -2.5,-2.8 2.5,2.8, body extent -4.05,-2.73 4.05,2.73, height 1.75
SOT-23-3 [mm]
  rect 0.65x1.05 smd: 1(-0.95,-1.15) 2(0.95,-1.15) 3(0,1.15)
  silkscreen extent -1.6,-0.75 1.6,0.72, body extent -1.5,-1.25 1.5,1.25, height 1.09
SOT-23-6 [mm] "SOT-23-6"
  rect 0.55x1.15 smd: 1(-0.95,-1.4) 2(0,-1.4) 3(0.95,-1.4) 4(0.95,1.4) 5(0,1.4) 6(-0.95,1.4)
  silkscreen extent -1.55,-0.53 1.55,0.52, body extent -1.5,-1.48 1.5,1.52, height 1.5
SOT-883 [mm] "SOT-883 L=1mm, W=0.6mm, H=0.39mm"
  rect 0.225x0.35 smd paste-0.025 mask+0.075: 1(-0.187,-0.325) 2(0.188,-0.325)
  rect 0.6x0.35 smd paste-0.05 mask+0.075: 3(0,0.325)
  silkscreen extent -0.57,-0.77 0.58,0.77, body extent -0.3,-0.5 0.3,0.5, height 0.4
SW_SMD_6mmX6mm_TL3301 [mm]
  rect 2.5x1.4 smd: 1(-4.55,2.25) 2(4.55,2.25) 3(-4.55,-2.25) 4(4.55,-2.25)
  silkscreen extent -3,-3 3,3, body extent -5,-3 5,3, height 5.12
TFBGA-100_P0.8_9X9X1.1 [mm]
  round 0.4 smd: A1(-3.6,3.6) A2(-2.8,3.6) A3(-2,3.6) A4(-1.2,3.6) A5(-0.4,3.6) A6(0.4,3.6) A7(1.2,3.6) A8(2,3.6) A9(2.8,3.6) A10(3.6,3.6) B1(-3.6,2.8) B2(-2.8,2.8) B3(-2,2.8) B4(-1.2,2.8) B5(-0.4,2.8) B6(0.4,2.8) B7(1.2,2.8) B8(2,2.8) B9(2.8,2.8) B10(3.6,2.8) C1(-3.6,2) C2(-2.8,2) C3(-2,2) C4(-1.2,2) C5(-0.4,2) C6(0.4,2) C7(1.2,2) C8(2,2) C9(2.8,2) C10(3.6,2) D1(-3.6,1.2) D2(-2.8,1.2) D3(-2,1.2) D4(-1.2,1.2) D5(-0.4,1.2) D6(0.4,1.2) D7(1.2,1.2) D8(2,1.2) D9(2.8,1.2) D10(3.6,1.2) E1(-3.6,0.4) E2(-2.8,0.4) E3(-2,0.4) E4(-1.2,0.4) E5(-0.4,0.4) E6(0.4,0.4) E7(1.2,0.4) E8(2,0.4) E9(2.8,0.4) E10(3.6,0.4) F1(-3.6,-0.4) F2(-2.8,-0.4) F3(-2,-0.4) F4(-1.2,-0.4) F5(-0.4,-0.4) F6(0.4,-0.4) F7(1.2,-0.4) F8(2,-0.4) F9(2.8,-0.4) F10(3.6,-0.4) G1(-3.6,-1.2) G2(-2.8,-1.2) G3(-2,-1.2) G4(-1.2,-1.2) G5(-0.4,-1.2) G6(0.4,-1.2) G7(1.2,-1.2) G8(2,-1.2) G9(2.8,-1.2) G10(3.6,-1.2) H1(-3.6,-2) H2(-2.8,-2) H3(-2,-2) H4(-1.2,-2) H5(-0.4,-2) H6(0.4,-2) H7(1.2,-2) H8(2,-2) H9(2.8,-2) H10(3.6,-2) J1(-3.6,-2.8) J2(-2.8,-2.8) J3(-2,-2.8) J4(-1.2,-2.8) J5(-0.4,-2.8) J6(0.4,-2.8) J7(1.2,-2.8) J8(2,-2.8) J9(2.8,-2.8) J10(3.6,-2.8) K1(-3.6,-3.6) K2(-2.8,-3.6) K3(-2,-3.6) K4(-1.2,-3.6) K5(-0.4,-3.6) K6(0.4,-3.6) K7(1.2,-3.6) K8(2,-3.6) K9(2.8,-3.6) K10(3.6,-3.6)
  silkscreen extent -4.7,-4.7 4.7,4.7, body extent -4.5,-4.5 4.5,4.5, height 1.05
TM5000_mockup_model [mm]
  round 0 hole 3.2 unplated mask+1.375: 1(-1.27,48.26) 1(0,0) 1(74.93,0) 1(81.28,48.26)
  L1 - Top Layer keep-out region: -1.27,45.26 -2.418,45.488 -3.391,46.139 -4.042,47.112 -4.27,48.26 -4.27,48.26 -4.042,49.408 -3.391,50.381 -2.418,51.032 -1.27,51.26 -1.27,51.26 -0.122,51.032 0.851,50.381 1.502,49.408 1.73,48.26 1.73,48.26 1.502,47.112 0.851,46.139 -0.122,45.488 -1.27,45.26
  L1 - Top Layer keep-out region: 81.28,45.26 80.132,45.488 79.159,46.139 78.508,47.112 78.28,48.26 78.28,48.26 78.508,49.408 79.159,50.381 80.132,51.032 81.28,51.26 81.28,51.26 82.428,51.032 83.401,50.381 84.052,49.408 84.28,48.26 84.28,48.26 84.052,47.112 83.401,46.139 82.428,45.488 81.28,45.26
  L1 - Top Layer keep-out region: 74.93,-3 73.782,-2.772 72.809,-2.121 72.158,-1.148 71.93,0 71.93,0 72.158,1.148 72.809,2.121 73.782,2.772 74.93,3 74.93,3 76.078,2.772 77.051,2.121 77.702,1.148 77.93,0 77.93,0 77.702,-1.148 77.051,-2.121 76.078,-2.772 74.93,-3
  L1 - Top Layer keep-out region: 0,-3 -1.148,-2.772 -2.121,-2.121 -2.772,-1.148 -3,0 -3,0 -2.772,1.148 -2.121,2.121 -1.148,2.772 0,3 0,3 1.148,2.772 2.121,2.121 2.772,1.148 3,0 3,0 2.772,-1.148 2.121,-2.121 1.148,-2.772 0,-3
  L4 - Bottom Layer keep-out region: -1.27,45.26 -2.418,45.488 -3.391,46.139 -4.042,47.112 -4.27,48.26 -4.27,48.26 -4.042,49.408 -3.391,50.381 -2.418,51.032 -1.27,51.26 -1.27,51.26 -0.122,51.032 0.851,50.381 1.502,49.408 1.73,48.26 1.73,48.26 1.502,47.112 0.851,46.139 -0.122,45.488 -1.27,45.26
  L4 - Bottom Layer keep-out region: 81.28,45.26 80.132,45.488 79.159,46.139 78.508,47.112 78.28,48.26 78.28,48.26 78.508,49.408 79.159,50.381 80.132,51.032 81.28,51.26 81.28,51.26 82.428,51.032 83.401,50.381 84.052,49.408 84.28,48.26 84.28,48.26 84.052,47.112 83.401,46.139 82.428,45.488 81.28,45.26
  L4 - Bottom Layer keep-out region: 74.93,-3 73.782,-2.772 72.809,-2.121 72.158,-1.148 71.93,0 71.93,0 72.158,1.148 72.809,2.121 73.782,2.772 74.93,3 74.93,3 76.078,2.772 77.051,2.121 77.702,1.148 77.93,0 77.93,0 77.702,-1.148 77.051,-2.121 76.078,-2.772 74.93,-3
  L4 - Bottom Layer keep-out region: 0,-3 -1.148,-2.772 -2.121,-2.121 -2.772,-1.148 -3,0 -3,0 -2.772,1.148 -2.121,2.121 -1.148,2.772 0,3 0,3 1.148,2.772 2.121,2.121 2.772,1.148 3,0 3,0 2.772,-1.148 2.121,-2.121 1.148,-2.772 0,-3
  body extent -31.5,-18 109.5,71.5, height 13
TP_1x1_SMD#1 [mm] "1.00mm SMD Pad"
  round 1 smd paste-1 mask+0.05: 1(0,0)
  body extent -0.5,-0.5 0.5,0.5, height 0.04
TP_1x1_SMD#2 [mm] "1.00mm SMD Pad"
  round 1 smd paste-1 mask+0.05: 1(-0.04,0)
  body extent -0.5,-0.5 0.5,0.5, height 0.04
TP_1x1_SMD#3 [mm] "1.00mm SMD Pad"
  round 1 smd paste-1 mask+0.05: 1(0,-0.175)
  body extent -0.5,-0.5 0.5,0.5, height 0.04
TSOP-48_P0.5 [mm]
  oval 1.7x0.3 smd: 1(-9.6,5.75) 2(-9.6,5.25) 3(-9.6,4.75) 4(-9.6,4.25) 5(-9.6,3.75) 6(-9.6,3.25) 7(-9.6,2.75) 8(-9.6,2.25) 9(-9.6,1.75) 10(-9.6,1.25) 11(-9.6,0.75) 12(-9.6,0.25) 13(-9.6,-0.25) 14(-9.6,-0.75) 15(-9.6,-1.25) 16(-9.6,-1.75) 17(-9.6,-2.25) 18(-9.6,-2.75) 19(-9.6,-3.25) 20(-9.6,-3.75) 21(-9.6,-4.25) 22(-9.6,-4.75) 23(-9.6,-5.25) 24(-9.6,-5.75) 25(9.6,-5.75) 26(9.6,-5.25) 27(9.6,-4.75) 28(9.6,-4.25) 29(9.6,-3.75) 30(9.6,-3.25) 31(9.6,-2.75) 32(9.6,-2.25) 33(9.6,-1.75) 34(9.6,-1.25) 35(9.6,-0.75) 36(9.6,-0.25) 37(9.6,0.25) 38(9.6,0.75) 39(9.6,1.25) 40(9.6,1.75) 41(9.6,2.25) 42(9.6,2.75) 43(9.6,3.25) 44(9.6,3.75) 45(9.6,4.25) 46(9.6,4.75) 47(9.6,5.25) 48(9.6,5.75)
  silkscreen extent -8.35,-6.1 8.35,6.1, body extent -10.1,-6.05 10.1,6.05, height 1.2
TSSOP-16 [mm] "TSOP, 16-Leads, Body 6.5x4.4mm (max), Pitch 0.65mm, IPC Medium Density"
  oval 1.45x0.45 smd: 1(-2.95,2.275) 2(-2.95,1.625) 3(-2.95,0.975) 4(-2.95,0.325) 5(-2.95,-0.325) 6(-2.95,-0.975) 7(-2.95,-1.625) 8(-2.95,-2.275) 9(2.95,-2.275) 10(2.95,-1.625) 11(2.95,-0.975) 12(2.95,-0.325) 13(2.95,0.325) 14(2.95,0.975) 15(2.95,1.625) 16(2.95,2.275)
  silkscreen extent -3.1,-2.6 1.8,3.1, body extent -3.2,-2.5 3.2,2.5, height 2.05
UQFN-16_4X4_EP2.6X2.6 [mm]
  rrect50% 0.8x0.35 smd paste+0 mask+0.075: 1(-2,0.975) 2(-2,0.325) 3(-2,-0.325) 4(-2,-0.975) 9(2,-0.975) 10(2,-0.325) 11(2,0.325) 12(2,0.975)
  rrect50% 0.35x0.8 smd paste+0 mask+0.057: 5(-0.975,-2) 6(-0.325,-2) 7(0.325,-2) 8(0.975,-2) 13(0.975,2) 14(0.325,2) 15(-0.325,2) 16(-0.975,2)
  rect 2.6x2.6 smd paste-0.25 mask+0.075: 17(0,0)
  silkscreen extent -2.15,-2.15 2.15,2.15, body extent -2,-2 2,2, height 0.5
US-8 [mm] "VFSOP-8, US-8, 0.5mm Pitch"
  oval 1.25x0.3 smd: 1(-1.325,0.75) 2(-1.325,0.25) 3(-1.325,-0.25) 4(-1.325,-0.75) 5(1.325,-0.75) 6(1.325,-0.25) 7(1.325,0.25) 8(1.325,0.75)
  silkscreen extent -0.4,-1.05 0.4,1.05, body extent -1.7,-1 1.7,1, height 0.68
WBGA-84_P0.8_8x12.5x1.2 [mm]
  round 0.4 smd: A1(-3.2,5.6) A2(-2.4,5.6) A3(-1.6,5.6) A7(1.6,5.6) A8(2.4,5.6) A9(3.2,5.6) B1(-3.2,4.8) B2(-2.4,4.8) B3(-1.6,4.8) B7(1.6,4.8) B8(2.4,4.8) B9(3.2,4.8) C1(-3.2,4) C2(-2.4,4) C3(-1.6,4) C7(1.6,4) C8(2.4,4) C9(3.2,4) D1(-3.2,3.2) D2(-2.4,3.2) D3(-1.6,3.2) D7(1.6,3.2) D8(2.4,3.2) D9(3.2,3.2) E1(-3.2,2.4) E2(-2.4,2.4) E3(-1.6,2.4) E7(1.6,2.4) E8(2.4,2.4) E9(3.2,2.4) F1(-3.2,1.6) F2(-2.4,1.6) F3(-1.6,1.6) F7(1.6,1.6) F8(2.4,1.6) F9(3.2,1.6) G1(-3.2,0.8) G2(-2.4,0.8) G3(-1.6,0.8) G7(1.6,0.8) G8(2.4,0.8) G9(3.2,0.8) H1(-3.2,0) H2(-2.4,0) H3(-1.6,0) H7(1.6,0) H8(2.4,0) H9(3.2,0) J1(-3.2,-0.8) J2(-2.4,-0.8) J3(-1.6,-0.8) J7(1.6,-0.8) J8(2.4,-0.8) J9(3.2,-0.8) K2(-2.4,-1.6) K3(-1.6,-1.6) K7(1.6,-1.6) K8(2.4,-1.6) K9(3.2,-1.6) L1(-3.2,-2.4) L2(-2.4,-2.4) L3(-1.6,-2.4) L7(1.6,-2.4) L8(2.4,-2.4) M2(-2.4,-3.2) M3(-1.6,-3.2) M7(1.6,-3.2) M8(2.4,-3.2) M9(3.2,-3.2) N1(-3.2,-4) N2(-2.4,-4) N3(-1.6,-4) N7(1.6,-4) N8(2.4,-4) P2(-2.4,-4.8) P3(-1.6,-4.8) P7(1.6,-4.8) P8(2.4,-4.8) P9(3.2,-4.8) R1(-3.2,-5.6) R2(-2.4,-5.6) R3(-1.6,-5.6) R7(1.6,-5.6) R8(2.4,-5.6)
  silkscreen extent -4.1,-6.35 4.1,6.35, body extent -4,-6.25 4,6.25, height 1.11

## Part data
C1 C2 C8 C10 C11 C12 C21 C22 C87 C89 C113 C114 C117 C119 C120 C123 C137 C138 C139 C140: library part CAP1418, "Capacitor", Manufacturer 1="Samsung Electro-Mechanics America, Inc", Manufacturer Part Number 1=CL31B106KAHNFNE, Operating Temperature="-55C to +125C", Package=1206, Supplier Part Number 1=1276-3100-1-ND, Temperature Coeffcient=X7R, Tolerance=10%, Voltage=25V
C3 C6 C7 C9 C14 C16 C17 C18 C19 C29 C53 C54 C55 C56 C58 C59 C60 C61 C69 C70 C75 C76 C77 C83 C84 C86 C88 C90 C93 C95 C96 C99 C100 C102 C103 C104 C105 C115 C118 C121 C124 C125 C129 C130 C133 C135 C136 C143 C144 C145 C146 C147 C153 C154 C155 C157 C158 C159 C160 C162 C163 C164 C165 C166 C167 C168 C169 C170 C173 C174 C175 C176 C177 C178 C179: library part CAP1463, "Capacitor", Manufacturer 1="TDK Corporation", Manufacturer Part Number 1=C1005X7R1H104K050BB, Operating Temperature="-55C to +125C", Package=0402, Supplier Part Number 1=445-5932-1-ND, Temperature Coeffcient=X7R, Tolerance=10%, Voltage=50V
C4 C116 C122: library part CAP1834, "Capacitor", Manufacturer 1="Wurth Electronics Inc.", Manufacturer Part Number 1=860010372006, Operating Temperature="-40°C 85°C", Package="Radial, Can", Supplier Part Number 1=732-8598-3-ND, Tolerance=±20%, Voltage=16V
C5 C13 C15 C31 C35 C39 C40 C47 C57 C65 C67 C68 C156 C161: library part CAP1684, "Capacitor", Manufacturer 1="TDK Corporation", Manufacturer Part Number 1=C1005X5R1A475K050BC, Operating Temperature="-55C to 85C", Package=0402, Supplier Part Number 1=445-13820-1-ND, Temperature Coeffcient=X5R, Tolerance=10%, Voltage=10V
C20 C64 C148 C149: library part CAP0278, "Capacitor", Manufacturer 1=KEMET, Manufacturer Part Number 1=C0402C103K4RACTU, Manufacturer Part Number 2=C0402C103K4RAC, Operating Temperature="-55C to +125C", Package=0402, Supplier Part Number 1=399-1038-1-ND, Temperature Coeffcient=X7R, Tolerance=10%, Voltage=16V
C23: library part CAP1762, "Capacitor", Manufacturer 1="Elna America", Manufacturer Part Number 1=DSK-3R3H204T614-H2L, Operating Temperature="-10C to +60C", Package=P8.3L11.7D6.8H1.8, Supplier Part Number 1=604-1147-1-ND, Tolerance="-20%, +80%", Voltage=3.3V
C24 C25: library part CAP0349, "Capacitor", Manufacturer 1=Murata, Manufacturer Part Number 1=GRM1555C1H270JA01D, Operating Temperature="-55C to +125C", Package=0402, Supplier Part Number 1=490-5869-1-ND, Temperature Coeffcient=NP0, Tolerance=5%, Voltage=50V
C26 C27 C91 C92 C106: library part CAP0364, "Capacitor", Manufacturer 1=Murata, Manufacturer Part Number 1=GRM1555C1H200JZ01D, Operating Temperature="-55C to +125C", Package=0402, Supplier Part Number 1=490-1282-1-ND, Temperature Coeffcient=C0G, Tolerance=5%, Voltage=50V
C28: library part CAP2024, "Capacitor", Manufacturer 1="Murata Electronics North America", Manufacturer Part Number 1=GRM033R61A105ME15D, Operating Temperature="-40C to +85C", Package=0201, Supplier Part Number 1=490-13226-1-ND, Temperature Coeffcient=X5R, Tolerance=20%, Voltage=10V
C32 C33 C34 C36 C37 C38 C41 C42 C43 C44 C45 C46 C48 C49 C50 C51 C63 C66 C71 C72 C73 C74 C78 C79 C80: library part CAP1203, "Capacitor", Manufacturer 1=Murata, Manufacturer Part Number 1=GRM033R61C104KE84D, Operating Temperature="-55C to +85C", Package=0201, Temperature Coeffcient=X5R, Tolerance=10%, Voltage=16V
C52: library part CAP1468, "Capacitor", Manufacturer 1="TDK Corporation", Manufacturer 2="Murata Electronics North America", Manufacturer Part Number 1=C1005X7S1A225K050BC, Manufacturer Part Number 2=GRM155C71A225KE11J, Operating Temperature="-55C to +125C", Package=0402, Supplier Part Number 1=445-9097-1-ND, Temperature Coeffcient=X7S, Tolerance=10%, Voltage=10V
C62: library part CAP1042, "Capacitor", Manufacturer 1=Murata, Manufacturer 2="Murata Electronics North America", Manufacturer 3="Panasonic Electronic Components", Manufacturer Part Number 1=GRM1555C1H220JZ01D, Manufacturer Part Number 2=GRM1555C1H220JA01D, Manufacturer Part Number 3=ECJ-0EC1H220J, Operating Temperature="-55C to +125C", Package=0402, Supplier Part Number 1=490-1283-2-ND, Temperature Coeffcient=NP0, Tolerance=5%, Voltage=50V
C81 C82 C128: library part CAP0566, "Capacitor", Manufacturer 1=TDK, Manufacturer Part Number 1=C1005C0G1E102J, Operating Temperature="-55C to +125C", Package=0402, Supplier Part Number 1=445-2651-1-ND, Temperature Coeffcient=C0G, Tolerance=5%, Voltage=25V
C85 C126 C127 C134 C171 C172: library part CAP0597, "Capacitor", Manufacturer 1=TDK, Manufacturer Part Number 1=C1608X5R1C225K, Operating Temperature="-55C to +85C", Package=0603, Supplier Part Number 1=445-5157-1-ND, Temperature Coeffcient=X5R, Tolerance=10%, Voltage=16V
C94 C98: library part CAP1391, "Capacitor", Manufacturer 1="Murata Electronics North America", Manufacturer Part Number 1=GRM155R71H472KA01D, Operating Temperature="-55C to 125C", Package=0402, Supplier Part Number 1=490-1308-1-ND, Temperature Coeffcient=X7R, Tolerance=10%, Voltage=50V
C97 C101: library part CAP0608, "Capacitor", Manufacturer 1=Murata, Manufacturer Part Number 1=GRM1555C1H150JA01D, Manufacturer Part Number 2=GRM1555C1H150JZ01D, Operating Temperature="-55C to +125C", Package=0402, Supplier Part Number 1=490-5888-2-ND, Temperature Coeffcient=NP0, Tolerance=5%, Voltage=50V
C131 C132: library part CAP1331, "Capacitor", Manufacturer 1="TDK Corporation", Manufacturer Part Number 1=C3216X5R1C476M160AB, Operating Temperature="-55C to +85C", Package=1206, Supplier Part Number 1=445-6003-1-ND, Temperature Coeffcient=X5R, Tolerance=20%, Voltage=16V
C141 C142: library part CAP0567, "Capacitor", Manufacturer 1=TDK, Manufacturer Part Number 1=C1005X7R1E103M, Operating Temperature="-55C to +125C", Package=0402, Supplier Part Number 1=445-4935-1-ND, Temperature Coeffcient=X7R, Tolerance=20%, Voltage=25V
C150: library part CAP0613, "Capacitor", Manufacturer 1=Murata, Manufacturer Part Number 1=GRM1555C1H100JZ01D, Manufacturer Part Number 2=GJM1555C1H100JB01D, Manufacturer Part Number 3=GRM1555C1H100JA01D, Operating Temperature="-55C to +125C", Package=0402, Supplier Part Number 1=490-1278-1-ND, Temperature Coeffcient=NP0, Tolerance=5%, Voltage=50V
C151 C152: library part CAP1379, "Capacitor", Manufacturer 1="Johanson Technology Inc", Manufacturer Part Number 1=500R07S8R2CV4T, Operating Temperature="-55C to 125C", Package=0402, Supplier Part Number 1=712-1293-1-ND, Temperature Coeffcient=NP0, Tolerance=0.25pF, Voltage=50V
D1 D5 D6 D8: library part DIODE0096, Forward Current=150mA, Manufacturer 1="Diodes Incorporated", Manufacturer Part Number 1=1N4148WS-7-F, Operating Temperature="-65C to +150C", Package=SOD-323, Power=200mW, Reverse Current=50uA, Reverse Voltage=75V, Supplier Part Number 1=1N4148WS-FDICT-ND
D2: library part DIODE0056, Forward Current=200mA, Manufacturer 1="Diodes Incorporated", Manufacturer 2=Fairchild, Manufacturer 4=STMicroelectronics, Manufacturer Part Number 1=BAT54CTA, Manufacturer Part Number 2=BAT54C, Manufacturer Part Number 3=UBAT54CTA, Operating Temperature="-55C to +150C", Package=SOT-23-3, Power=330mW, Reverse Current=2.5uA, Reverse Voltage=30V, Supplier Part Number 1=BAT54CTR-ND
D3: library part DIODE1254, "DIO SCTKY RB160M-60TR 550mV 1A 60V SMD SOD-123F", Forward Current=1A, Manufacturer 1="NXP Semiconductors                                                                               NXP Semiconductors", Manufacturer Part Number 1=PMEG6010ER,115, Operating Temperature="-65C to +150C", Package=SOD-123, Power=0.95W, Reverse Current=60uA, Reverse Voltage=60V, Supplier Part Number 1=568-7412-1-ND
D4 D7 D9: library part DIODE1110, "LED", Forward Current=30mA, Manufacturer 1="Kingbright Corp", Manufacturer Part Number 1=APHBM2012SURKCGKC, Operating Temperature="-40C to +85C", Package=0805, Power=75mW, Reverse Current=10uA, Supplier Part Number 1=754-1093-1-ND
FB1 FB2 FB3: library part IND1453, Manufacturer 1="Murata Electronics North America", Manufacturer Part Number 1=BLM18PG181SN1D, Operating Temperature="-55C to +125C", Package=0603, Saturation Current=1.5A, Supplier Part Number 1=490-5263-1-ND, Test Frequency=100MHz
FB5 FB6 FB7 FB8 FB9 FB10 FB11 FB12 FB13: library part IND1453, "FERRITE 180R 1.5A SMD 0603", Manufacturer 1="Murata Electronics North America", Manufacturer Part Number 1=BLM18PG181SN1D, Operating Temperature="-55C to +125C", Package=0603, Saturation Current=1.5A, Supplier Part Number 1=490-5263-1-ND, Test Frequency=100MHz
J1: library part CON1560, Manufacturer 1="MPD (Memory Protection Devices)", Manufacturer Part Number 1=EJ508A, Supplier Part Number 1=EJ508A-ND
J2 J3 J13 J19 J20 J21: library part CON1312, Manufacturer 1="Sullins Connector Solutions", Manufacturer 2="SHENZHEN JUNHAO ENGINEERING", Manufacturer Part Number 1=PREC002SAAN-RC, Manufacturer Part Number 2=R-211-0211-0021-000, Supplier Part Number 1=S1012EC-02-ND
J4: library part CON1752, Current=500mA, Manufacturer 1="Amphenol FCI", Manufacturer Part Number 1=10067847-001RLF, Supplier Part Number 1=609-3956-1-ND, Voltage=17V
J5: library part CON1769, Manufacturer 1="Pulse Electronics Network", Manufacturer Part Number 1=J00-0045NL, Supplier Part Number 1=553-1619-5-ND
J6: library part CON1693, Current=13.5A, Manufacturer 1="Phoenix Contact", Manufacturer Part Number 1=1727049, Supplier Part Number 1=277-1950-ND, Voltage=300
J7 J22: library part CON1383, "Connector USB Mini", Manufacturer 1=FCI, Manufacturer 2=YangMing, Manufacturer Part Number 1=10118194-0001LF, Manufacturer Part Number 2=YM-02-363-N05F, Supplier Part Number 1=609-4618-1-ND
J8: library part CON1430, "Connector USB DUAL", Current=1.5A, Manufacturer 1="Assmann WSW Components", Manufacturer Part Number 1=AU-Y1008-2, Supplier Part Number 1=AE11131-ND
J9: library part CON1425, Manufacturer 1="TE Connectivity AMP Connectors", Manufacturer Part Number 1=5-534237-1, Supplier Part Number 1=A32904-ND
J10: library part CON1363, "CON HDR-2.54 Female 1x8 Gold TH", Manufacturer 1="Sullins Connector Solutions", Manufacturer 2=Nextron, Manufacturer Part Number 1=PPPC081LFBN-RC, Manufacturer Part Number 2=R-212-0810-0071-000, Supplier Part Number 1=S7041-ND
J11: library part CON0465, Manufacturer 1=Samtec, Manufacturer 2="SHENZHEN JUNHAO ENGINEERING", Manufacturer Part Number 1=TSW-103-07-T-S, Manufacturer Part Number 2=R-211-0311-0021-000, Supplier Part Number 1=SAM1035-03-ND
J12: library part CON0005, Current=6A, Manufacturer 1="Phoenix Contact", Manufacturer 2="Degson Electronics Co., Ltd.", Manufacturer Part Number 1=1725672, Manufacturer Part Number 2=DG308-2.54-04P-14-00A(H), Supplier Part Number 1=277-1275-ND, Voltage=63V
J14: library part SKT1042, Manufacturer 1="Sullins Connector Solutions", Manufacturer 2=Nextron, Manufacturer Part Number 1=PPTC081LFBN-RC, Manufacturer Part Number 2=R-212-0810-0071-000, Package="mikroBUS HOST", Supplier Part Number 1=S7006-ND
